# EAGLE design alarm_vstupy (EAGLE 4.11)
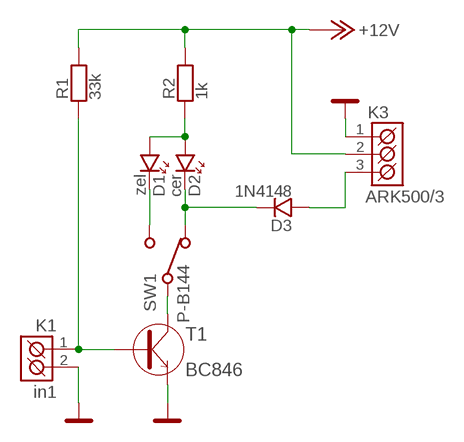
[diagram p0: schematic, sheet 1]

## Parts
D1  zel  LED_3  [LED_3]
D2  cer  LED_3  [LED_3]
D3  1N4148  1N4148_SMD_SOD80  [SOD-80]
K1  in1  ARK500/2  [ARK500/2]
K3  ARK500/3  [ARK500/3]
R1  33k  R_SMD_1206  [1206]
R2  1k  R_SMD_1206  [1206]
SW1  P-B144  [P-B144]
T1  BC846  [SOT-23]

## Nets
+12V: K3.2(K2) R1.2 R2.2
ALARM: D3.A K3.3(K3)
GND: K1.2(K2) K3.1(K1) T1.1(E)
N$1: K1.1(K1) R1.1 T1.2(B)
N$2: SW1.2 T1.3(C)
N$3: D1.A D2.A R2.1
N$4: D1.K SW1.1
N$6: D2.K D3.K SW1.3

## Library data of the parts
D1 D2 = #PaJa_13:LED: LED - jednobarevna
D3 = #PaJa_13:1N4148: Univerzalni dioda - 0,15A, 75V
K1 = #PaJa_13:ARK500/2: Svorkovnice - roztec 5mm - dvojita
K3 = #PaJa_14:ARK500/3: Svorkovnice - roztec 5mm - trojita
R1 R2 = #PaJa_13:R: Rezistor
SW1 = #PaJa_14:P-B144
T1 = #PaJa_14:BC846: SMD tranzistor - NPN - ekv. BC546

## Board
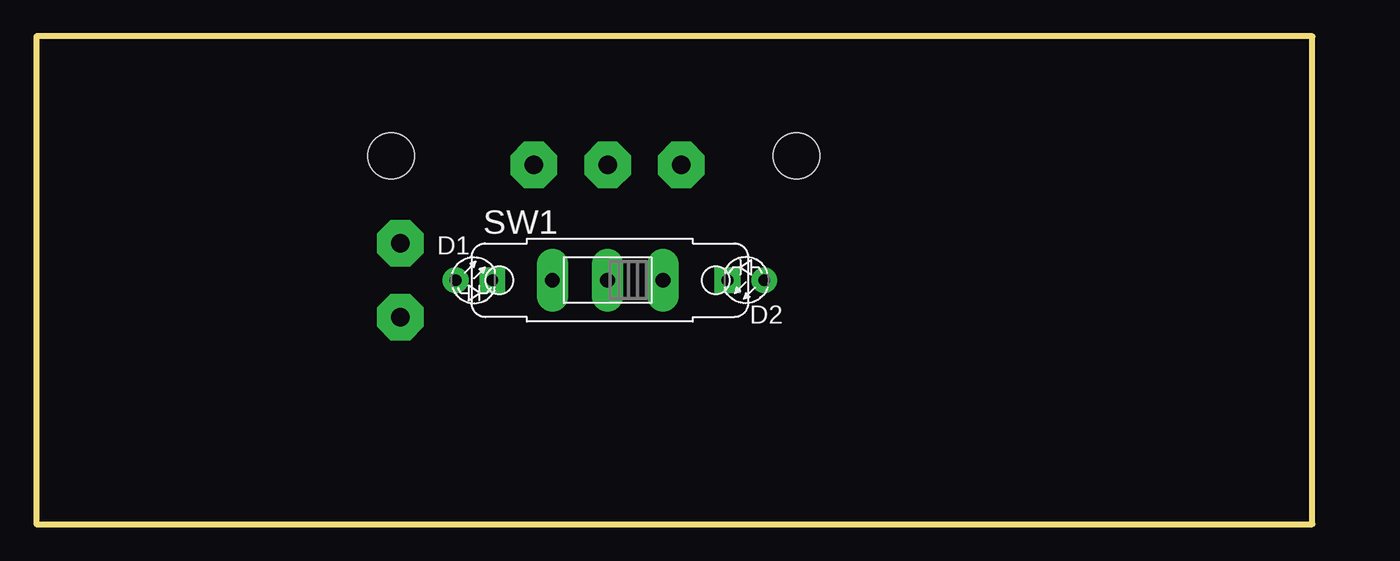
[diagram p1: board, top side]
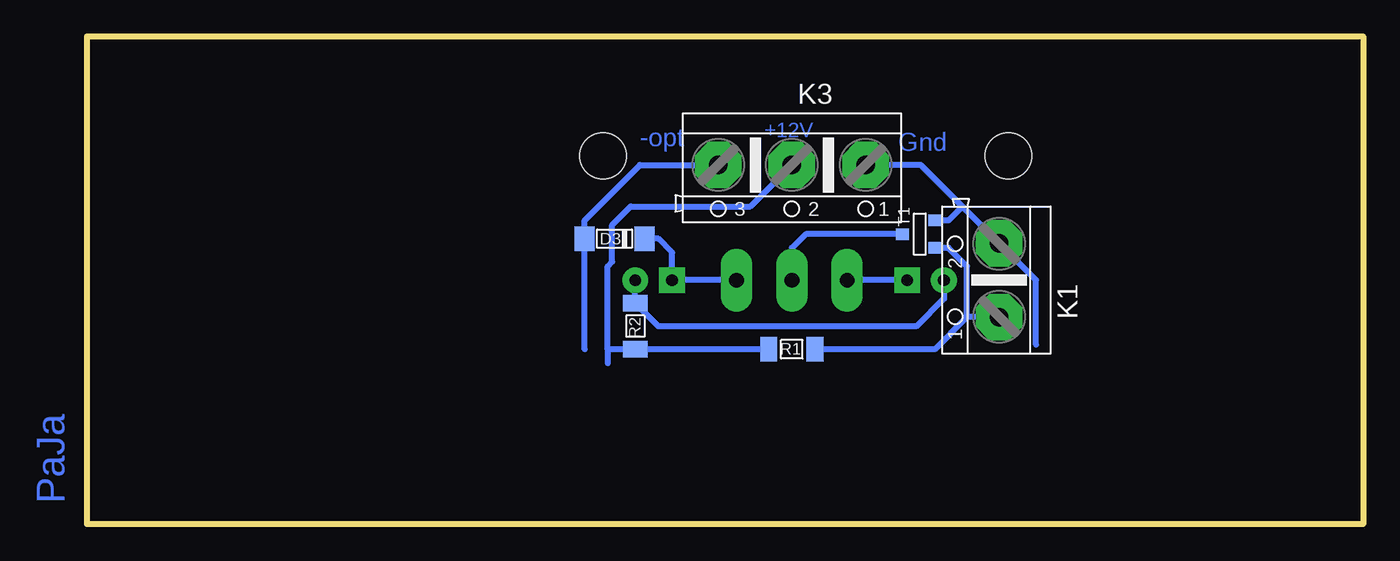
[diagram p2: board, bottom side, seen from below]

Size 87.94 x 33.65 mm. Coordinates in mm from the lower left corner, seen from the top.
Outline: 0,0 87.94,0 87.94,33.65 0,33.65 0,0
Copper layers (1*16): Top 0.035mm / dielectric 1.5mm / Bottom 0.035mm
Design rules "default": minimum track width 10mil, minimum drill 24mil, track to track 8mil, track to pad 8mil, pad to pad 8mil, via to via 8mil, smd to smd 8mil, copper to edge 40mil, drill to drill 8mil, minimum pad ring 10mil, minimum via ring 8mil, stop-mask expansion 4mil, vias tented up to drill 0mil, thermal gap 10mil
Holes 3.2 mm at 24.45,25.4 52.39,25.4

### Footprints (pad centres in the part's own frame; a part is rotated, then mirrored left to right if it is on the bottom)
LED_3 = drill 0.813 pad 1.778 round: A -1.27,0 | drill 0.813 pad 1.778 square: K 1.27,0
SOD-80 = smd 1.397 x 1.702: A 1.905,0; K -2.223,0
ARK500/2 = drill 1.27 pad 3.2 octagon: 1 -2.54,0; 2 2.54,0
ARK500/3 = drill 1.27 pad 3.2 octagon: 1 -5.08,0; 2 0,0; 3 5.08,0
1206 = smd 1.143 x 1.702: 1 -1.587,0; 2 1.587,0
P-B144 = drill 1.016 pad 2.184 long: 1 -3.81,0; 2 0,0; 3 3.81,0
SOT-23 = smd 0.787 x 0.889: 1 0.953,-0.953; 2 -0.953,-0.953; 3 0,1.27

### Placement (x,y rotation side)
D1  30.16,16.83 0 top
D2  48.9,16.83 180 top
D3  51.75,19.68 180 bottom
K1  25.08,16.83 90 bottom
K3  39.37,24.77 180 bottom
R1  39.37,12.06 180 bottom
R2  50.16,13.65 270 bottom
SW1  39.37,16.83 0 top
T1  30.48,20 90 bottom

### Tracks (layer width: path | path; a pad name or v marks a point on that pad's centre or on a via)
+12V
  Bottom 0.406: K3.2 42.23,21.91 50.48,21.91 51.75,20.64 51.75,18.1 52.07,17.78 52.07,12.06 | R1.2 R2.2 52.07,12.06 | 52.07,12.06 52.07,11.11
ALARM
  Bottom 0.406: K3.3 49.85,24.77 53.66,20.95 D3.A 53.66,12.06
GND
  Bottom 0.406: K3.1 30.48,24.77 27.62,21.91 | 22.54,12.38 22.54,16.83 K1.2 27.62,21.91 | T1.1 28.57,20.95 27.62,21.91
N$1
  Bottom 0.406: T1.2 28.57,19.05 27.3,17.78 27.3,14.29 | R1.1 29.53,12.06 27.3,14.29 | K1.1 27.3,14.29
N$2
  Bottom 0.406: T1.3 38.42,20 39.37,19.05 SW1.2
N$3
  Bottom 0.406: D1.A 28.89,15.56 30.8,13.65 48.58,13.65 R2.1 D2.A
N$4
  Bottom 0.406: D1.K SW1.1
N$6
  Bottom 0.406: SW1.3 D2.K 47.62,18.73 48.58,19.68 D3.K

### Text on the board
Bottom: +12V | Gnd | -opt | PaJa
